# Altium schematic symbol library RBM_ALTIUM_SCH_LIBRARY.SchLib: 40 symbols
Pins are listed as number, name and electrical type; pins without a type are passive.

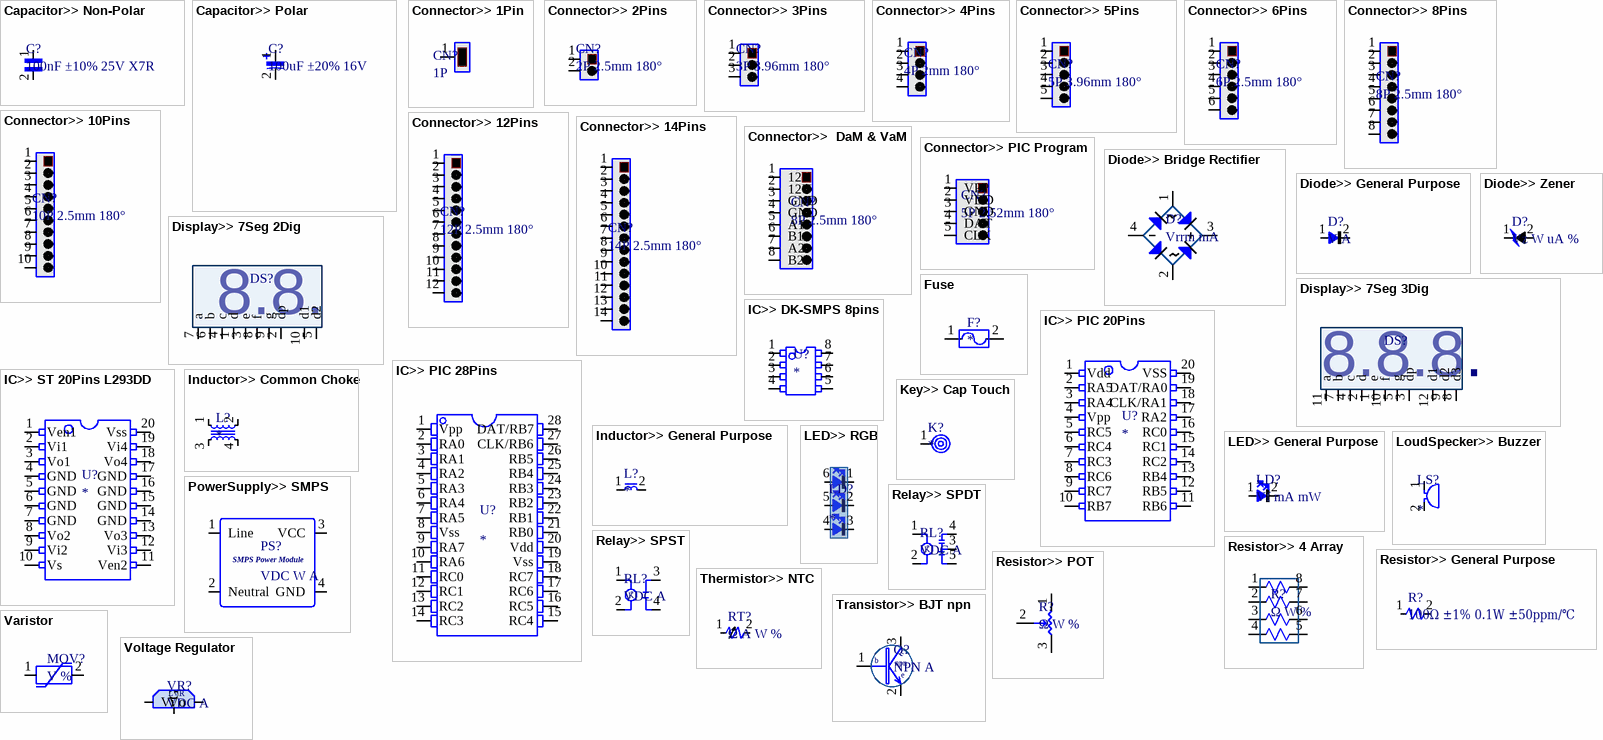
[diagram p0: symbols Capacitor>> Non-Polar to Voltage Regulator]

## Capacitor>> Non-Polar
designator C?, comment 100nF ±10% 25V X7R
footprint C_0805
footprint C_X1_P10
footprint C_X2_18X10X15.8_P15
footprint C_X2_26X12X21.5_P22.5
footprint C_0603 (0603 Multilayer Ceramic Capacitors MLCC - SMD/SMT RoHS)
pins: 1, 2

## Capacitor>> Polar
designator C?, comment 100uF ±20% 16V
footprint C_Radial_Ø5*11mm_P2
footprint C_Radial_Ø5*11mm_P2_Right_Angle
footprint C_Radial_Ø5*11mm _P2_Right_Angle_without_3d
footprint C_Radial_Ø6.3*11mm_P2.5
footprint C_Radial_Ø8*11mm_P3.5
footprint C_SMD_Ø4*5.4mm
footprint C_SMD_Ø5*5.4mm
footprint C_SMD_Ø6.3*5.4mm (SMD 6.3x5.4mm Aluminum Electrolytic Capacitors - SMD RoHS)
pins: 1, 2

## Connector>> 1Pin
designator CN?, comment 1P
footprint CN_Tab Terminal 187 series (Right Angle)
footprint CN_Tab Terminal 187 series (Straight)
footprint CN_Tab Terminal 250 series (Right Angle)
footprint CN_Tab Terminal 250 series (Straight)
footprint CN_Ø1.25mm_Lead (Lead Wire)
pins: 1

## Connector>> 2Pins
designator CN?, comment 2P 2.5mm 180°
footprint CN_B2B-XH-A_RED
footprint CN_B2B-XH-A_WHITE
footprint CN_PIC_MCU_Reseter_Straight
footprint CN_B2P-VH_BLUE (3.96mm Pitch)
footprint CN_B3P-VH_BLUE_AC (3.96mm Pitch)
pins: 1, 2

## Connector>> 3Pins
designator CN?, comment 3P 3.96mm 180°
footprint CN_B3P-VH_BLUE_DC (3.96mm Pitch)
pins: 1, 2, 3

## Connector>> 4Pins
designator CN?, comment 4P 2mm 180°
footprint CN_4P_A2001WR-S-XP-LCP
footprint CN_4P_A2001WV-XP-180DEG (Top Entry Header 1.25mm pitch 1X4pin  180° long)
pins: 1, 2, 3, 4

## Connector>> 5Pins
designator CN?, comment 5P 3.96mm 180°
footprint CN_B5P-VH_BLUE (3.96mm Pitch)
pins: 1, 2, 3, 4, 5

## Connector>> 6Pins
designator CN?, comment 6P 2.5mm 180°
footprint CN_B6B-XH-A_BLUE (2.5mm Pitch, 8pins, Top-Entry, XH Connector)
pins: 1, 2, 3, 4, 5, 6

## Connector>> 8Pins
designator CN?, comment 8P 2.5mm 180°
footprint CN_B8B-XH-A_BLUE (2.5mm Pitch, 8pins, Top-Entry, XH Connector)
pins: 1, 2, 3, 4, 5, 6, 7, 8

## Connector>> 10Pins
designator CN?, comment 10P 2.5mm 180°
footprint CN_B10B-XH-A_BLUE (2.5mmPitch, TopEntry, BlueColor, XH Connector)
pins: 1, 2, 3, 4, 5, 6, 7, 8, 9, 10

## Connector>> 12Pins
designator CN?, comment 12P 2.5mm 180°
footprint CN_B12B-XH-A_BLUE (2.5mmPitch, TopEntry, BlueColor, XH Connector)
pins: 1, 2, 3, 4, 5, 6, 7, 8, 9, 10, 11, 12

## Connector>> 14Pins
designator CN?, comment 14P 2.5mm 180°
footprint CN_B14B-XH-A_BLUE (2.5mmPitch, TopEntry, BlueColor, XH Connector)
pins: 1, 2, 3, 4, 5, 6, 7, 8, 9, 10, 11, 12, 13, 14

## Connector>>  DaM & VaM
designator CN?, comment 8P 2.5mm 180°
footprint CN_B8B-XH-A_BLUE
pins: 1 12V, 2 12V, 3 GND, 4 GND, 5 A1, 6 B1, 7 A2, 8 B2

## Connector>> PIC Program
designator CN?, comment 5P 2.52mm 180°
footprint CN_PIC_MCU_Debugger_RightAngle
footprint CN_PIC_MCU_Debugger_Straight
pins: 1 VPP, 2 VDD, 3 GND, 4 DAT, 5 CLK

## Diode>> Bridge Rectifier
designator D?, comment Vrrm mA
footprint D_SMD_ABS10
footprint D_SMD_MB6S
pins: 1 AC, 2 AC, 3 VCC, 4 vss

## Diode>> General Purpose
designator D?, comment V A
footprint D_SOT-23-3_200mA (Diodes - General Purpose 100V 200mA 1.25V @ 200mA SOT-23(SOT-23-3) RoHS)
footprint D_DO214AC-ES1J (Molded Diode, 2-Leads, Body 4.29x2.69mm, IPC Medium Density)
pins: 1 A, 2 K

## Diode>> Zener
designator D?, comment Vz W uA %
footprint D_SMD_LL-41
pins: 1 A, 2 K

## Display>> 7Seg 2Dig
designator DS?  (value not drawn)
footprint DS_56" 2 digit Display
pins: 1 d, 2 dp, 3 e, 4 c, 5 d2, 6 b, 7 a, 8 f, 9 g, 10 d1

## Display>> 7Seg 3Dig
designator DS?  (value not drawn)
footprint DS_56" 3 digit Display
pins: 1 e, 2 d, 3 dp, 4 c, 5 g, 7 b, 8 d3, 9 d2, 10 f, 11 a, 12 d1

## Fuse
designator F?
footprint F_4x8_P5
pins: 1, 2

## IC>> DK-SMPS 8pins
designator U?
footprint U_DK912_TH
pins: 1, 2, 3, 4, 5, 6, 7, 8

## IC>> PIC 20Pins
designator U?
footprint U_PIC_20Pin_SOIC (SOIC, 20-Leads, Body 12.80x7.50mm, Pitch 1.27mm, IPC Medium Density)
footprint U_PIC_20pin_SSOP (SOP, 20-Leads, Body 7.20x5.30mm, Pitch 0.65mm, IPC Medium Density)
pins: 1 Vdd, 2 RA5, 3 RA4, 4 Vpp, 5 RC5, 6 RC4, 7 RC3, 8 RC6, 9 RC7, 10 RB7, 11 RB6, 12 RB5, 13 RB4, 14 RC2, 15 RC1, 16 RC0, 17 RA2, 18 CLK/RA1, 19 DAT/RA0, 20 VSS

## IC>> PIC 28Pins
designator U?
footprint U_PIC16F18856_SSOP (SOP, 28-Leads, Body 10.20x5.30mm, Pitch 0.65mm, Thermal Pad 8.00x4.00mm, IPC Medium Density)
pins: 1 Vpp, 2 RA0, 3 RA1, 4 RA2, 5 RA3, 6 RA4, 7 RA5, 8 Vss, 9 RA7, 10 RA6, 11 RC0, 12 RC1, 13 RC2, 14 RC3, 15 RC4, 16 RC5, 17 RC6, 18 RC7, 19 Vss, 20 Vdd, 21 RB0, 22 RB1, 23 RB2, 24 RB3, 25 RB4, 26 RB5, 27 CLK/RB6, 28 DAT/RB7

## IC>> ST 20Pins L293DD
designator U?
footprint U_L293DD (SOIC, 20-Leads, Body 12.80x7.50mm, Pitch 1.27mm, Thermal Pad 9.00x4.60mm, IPC Medium Density)
pins: 1 Ven1, 2 Vi1, 3 Vo1, 4 GND, 5 GND, 6 GND, 7 GND, 8 Vo2, 9 Vi2, 10 Vs, 11 Ven2, 12 Vi3, 13 Vo3, 14 GND, 15 GND, 16 GND, 17 GND, 18 Vo4, 19 Vi4, 20 Vss

## Inductor>> Common Choke
designator L?
footprint L_Common_Mode_Choke_7mmx8mm Pitch (1~22mH, 1000~200mA)
pins: 1, 2, 3, 4

## Inductor>> General Purpose
designator L?
footprint L_6x10_P3
pins: 1, 2

## Key>> Cap Touch
designator K?
footprint K_Cap-Touch_10H-8W-0.6D
footprint K_Cap-Touch_12H-9W-0.6&1.3D
footprint K_Cap-Touch_15H-8W-0.5D
footprint K_Cap-Touch_with_LED-Option
pins: 1

## LED>> General Purpose
designator LD?, comment Vf mA mW
footprint LED_3x5_P2.5
footprint LED_SMD3528
footprint LED_SMD2835
footprint LED_SMD0603
pins: 1 vdd, 2 vss

## LED>> RGB
designator LD?
footprint LED_PLCC5050 (EDISON RGB .2W)
pins: 1, 2, 3, 4, 5, 6

## LoudSpecker>> Buzzer
designator LS?
footprint LS_12.2x6.5_P5_PS1240P02BT
pins: 1 vdd, 2 vss

## PowerSupply>> SMPS
designator PS?, comment VDC W A
footprint PS_HP03S1200WJ_SMPS_12VDC-3W
footprint PS_ZP10S1200W_SMPS_12VDC-10W
pins: 1 Line, 2 Neutral, 3 VCC, 4 GND

## Relay>> SPDT
designator RL?, comment VDC A
footprint RL_SPDT_10ARelay_AZ943-1CH-12DE
pins: 1, 2, 3 COM, 4 NO, 5 NC

## Relay>> SPST
designator RL?, comment VDC A
footprint RL_SPST_5ARelay_AZ7709-1AB-12DE
footprint RL_SPST_15ARelay_AZ943-1AH-12DE
pins: 1, 2, 3, 4

## Resistor>> 4 Array
designator R?, comment Ω W %
footprint R_0603_4_array (Chip Array, Concave, 8-Leads, Pitch 0.80mm,  Body 3.20x1.60mm,  IPC Medium Density)
pins: 1, 2, 3, 4, 5, 6, 7, 8

## Resistor>> General Purpose
designator R?, comment 100Ω ±1% 0.1W ±50ppm/℃
footprint R_0805
footprint R_1206
footprint R_2512 (Chip Resistor, 2-Leads, Body 6.35x3.10mm, IPC Medium Density)
footprint R_Axial_P15 (Resistors 12mm Length)
footprint R_Axial_P10 (Resistors 7mm Length)
footprint R_Axial_P13 (Resistors 10.5mm Length)
footprint R_Radial_P5 (All Through Hole Resistors)
footprint R_1812 (Chip Resistor, 2-Leads, Body 4.50x3.00mm, IPC Medium Density)
footprint R_0603 (RK73G1JTTD1000F; 0603 Chip Resistor - Surface Mount RoHS)
pins: 1, 2

## Resistor>> POT
designator R?, comment Ω W %
footprint R_POT
pins: 1 VDD, 2 POT, 3 VSS

## Thermistor>> NTC
designator RT?, comment Ω A W %
footprint NTC_5mmPitch
pins: 1, 2

## Transistor>> BJT npn
designator Q?, comment NPN A
footprint Q_SOT-23_NPN (NPN 200mA 40V 250mW SOT-23(SOT-23-3))
pins: 1 Base, 2 Emitter, 3 Collector

## Varistor
designator MOV?, comment V %
footprint MOV_10D471
pins: 1, 2

## Voltage Regulator
designator VR?, comment VDC A
footprint VR_SOT89 (SOT89, 3-Leads, Body 4.50x2.45mm, Pitch 1.50mm, Lead Span 4.1mm - Reverse Pinning, IPC Medium Density)
footprint VR_TO-252-2(DPAK) (D-PAK, 3-Pads, Body 6.20x6.61mm (max), IPC Medium Density)
pins: GND G, V-IN Vi, V-OUT Vo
